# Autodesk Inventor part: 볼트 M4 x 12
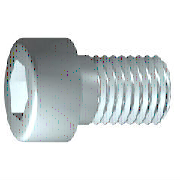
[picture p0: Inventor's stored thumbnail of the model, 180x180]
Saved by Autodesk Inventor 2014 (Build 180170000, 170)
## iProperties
IsCustomPart: 0
Created: 2012-02
Part Number: 볼트 M4 x 12
Material: 강철, 연강
Description: 6각 소켓 머리 캡 나사
Document SubType Name: Modeling
Standard: ISO 4762
Designer: mduedu
Standard Revision: Fourth edition 2004-03-01
Standards Organization: ISO
Language: ko-KR
Size Designation: M4 x 12
Categories: <MemberInstance><Categories><Category DisplayName="조임쇠" InternalName="e4da775c-781d-43d5-af7c-5136215cf5a6" Mnemonic="FSTN"><Category DisplayName="볼트" InternalN
Density: 7.86 g/cm^3
Appearance: 강철
Mass: 2.23465 g
Surface Area: 3.30853 cm^2
Volume: 0.284306 cm^3
Author: mduedu
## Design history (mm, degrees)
sketch "스케치1"
  geometry: L1 (-1, 0)-(12, 0); L2 (12, 0)-(12, 2); L3 (12, 2)-(1.75, 2); L4 (1.75, 2)-(1.32, 2); L5 (1.32, 2)-(0, 2); L6 (0, 2)-(0, 3.5); L7 (0, 3.5)-(-4, 3.5); L8 (-4, 3.5)-(-4, 1.732); L9 (-4, 1.732)-(-2, 1.732); L10 (-2, 1.732)-(-1, 0); L11 (-7.2, 0)-(15.2, 0) reference; L12 (0, -0.7)-(0, 4.2) reference; L13 (1.75, 2)-(0, 2)
  constraints: 22 end point, 6 parallel, 2 collinear, 2 perpendicular, 1 horizontal, 1 point on line
  dimensions: "d1" = 10.25 distance from line of L3.end L2 (= GEL); "d2" = 0.42952 distance of L4.end L3.end (computed from GAL); "d3" = 4 distance between parallel lines of L8 L6 (= KOH); "d4" = 2 distance of L8.end L9.end (= INTI); "d5" = 60 deg angle of L10 L1; "d6" = 4 diameter of L3 L1 (= GD); "d7" = 4 diameter of L5 L1 (= BDM); "d8" = 3.4641 diameter of L9 L1 (= 1.1547 x SW); "d9" = 7 diameter of L7 L1 (= KOD); "d26" = 12 distance between parallel lines of L12 L2 (= NLG)
revolve "본체" sketch "스케치1" stored, may be unused: angle "d10" = 90 deg
sketch "스케치2"
  geometry: L1 (0, -4.9)-(0, 4.9) reference; L2 (-4.9, 0)-(4.9, 0) reference; L3 (1.732, 0)-(0.866, -1.5); L4 (0.866, -1.5)-(-0.866, -1.5); L5 (-0.866, -1.5)-(-1.732, 0); L6 (-1.732, 0)-(-0.866, 1.5); L7 (-0.866, 1.5)-(0.866, 1.5); L8 (0.866, 1.5)-(1.732, 0); 2 further points
  constraints: 12 end point, 1 coincident, 1 horizontal alignment, 1 point on line, 12 other
extrude "슬롯" join sketch "스케치2" stored distance "d11" = 10; taper "d12" = 0 deg
workplane "Work Plane1"
fillet "Fillet2" dims "d30" = 0.1 (= R)
body "Solid1"
fillet "모깎기1" dims "d17" = 0.4 (= RR)
feature "스레드" dims "d13" = 10.25 (= GEL), "d14" = 0
chamfer "모따기1" distance "d15" = 0.42941 (= -0.5 x SPD + 0.5 x GD); stored, may be unused: second distance "d16" = 0.42941 (= GUL), angle "d27" = 45 deg
other parameters: "GD" = 4 [user parameter; used in 2 equation terms], "NLG" = 12 [user parameter; used in 1 equation term], "GEL" = 10.25 [user parameter; used in 2 equation terms], "KOD" = 7 [user parameter; used in 1 equation term], "KOH" = 4 [user parameter; used in 1 equation term], "INTI" = 2 [user parameter; used in 1 equation term], "GAL" = 0.42941 (= 0.61345 x PTC) [user parameter; used in 1 equation term], "GUL" = 0.42941 (= 0.61345 x PTC) [user parameter; used in 1 equation term], "BDM" = 4 (= NND) [user parameter; used in 1 equation term], "SW" = 3 [user parameter; used in 2 equation terms], "RR" = 0.4 [user parameter; used in 1 equation term], "SPD" = 3.14117 (= NND - 1.2269 x PTC) [user parameter; used in 1 equation term], "d19" = 0, "d28" = 0, "d29" = 0, "R" = 0.1 [user parameter; used in 1 equation term], "TOA" = 30 deg [user parameter], "GD1" = 3.14117 (= THREADDIA - 1.2269 x PTC) [user parameter], "THREADDIA" = 4 [user parameter; used in 1 equation term], "FAWI" = 45 deg [user parameter], "TPU" = 14.28571 (computed from PTC) [user parameter], "PTC" = 0.7 [user parameter; used in 5 equation terms], "NND" = 4 [user parameter; used in 2 equation terms], "E0" = 3.465 (= 1.155 x SW) [user parameter]
